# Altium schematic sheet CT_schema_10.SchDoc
size 274 x 160 mm
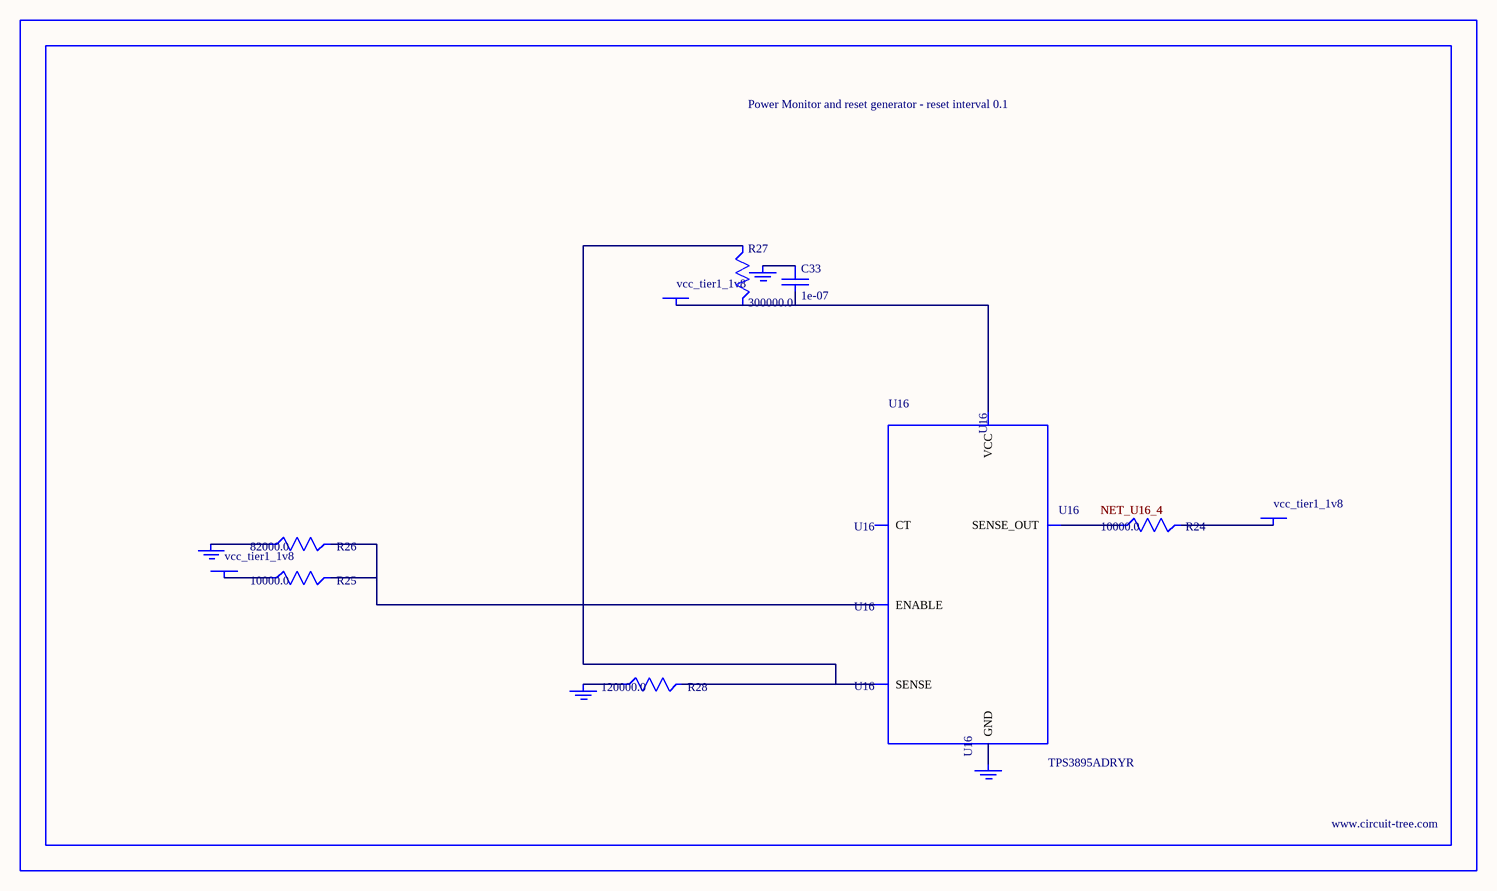
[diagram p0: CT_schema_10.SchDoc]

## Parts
BORDER9  (no value)
C33  1e-07  [C0402]
GND_INSTANCE_9_0  (no value)
GND_INSTANCE_9_1  (no value)
GND_INSTANCE_9_2  (no value)
GND_INSTANCE_9_3  (no value)
POWER_INSTANCE_9_0  vcc_tier1_1v8
POWER_INSTANCE_9_1  vcc_tier1_1v8
POWER_INSTANCE_9_2  vcc_tier1_1v8
R24  10000.0  [R0603]
R25  10000.0  [R0603]
R26  82000.0  [R0603]
R27  300000.0  [R0603]
R28  120000.0  [R0603]
U16  TPS3895ADRYR  [SON-6]

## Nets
NetC33_1: C33.1 GND_INSTANCE_9_2.0(GND)
NetC33_2: C33.2 POWER_INSTANCE_9_2.0(PWR) R27.2 U16.6(VCC)
NetGND_INSTANCE_9_0_0: GND_INSTANCE_9_0.0(GND) R26.1
NetGND_INSTANCE_9_1_0: GND_INSTANCE_9_1.0(GND) R28.1
NetGND_INSTANCE_9_3_0: GND_INSTANCE_9_3.0(GND) U16.2(GND)
NetPOWER_INSTANCE_9_0_0: POWER_INSTANCE_9_0.0(PWR) R25.1
NetPOWER_INSTANCE_9_1_0: POWER_INSTANCE_9_1.0(PWR) R24.2
NetR24_1: R24.1 U16.4(SENSE_OUT)
NetR25_2: R25.2 R26.2 U16.1(ENABLE)
NetR27_1: R27.1 R28.2 U16.3(SENSE)

Not connected (* = marked no-connect by the designer): U16 5(CT)

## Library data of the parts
BORDER9 = BORDER_PAGE9
C33 = C0402C104K3RACTU
GND_INSTANCE_9_0-GND_INSTANCE_9_3 = GND
POWER_INSTANCE_9_0-POWER_INSTANCE_9_2 = PWR
R24 R25 = RC0603JR-0710KL
R26 = RC0603JR-0782KL
R27 = RC0603JR-07300KL
R28 = RC0603JR-07120KL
